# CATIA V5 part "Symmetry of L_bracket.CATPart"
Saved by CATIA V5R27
Part number: Symmetry of L_bracket
Bounding box of the stored display mesh (mm): x 0 to 76.2, y -76.2 to 0, z -16.637 to 16.637
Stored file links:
  \\triton.meca.polymtl.ca\usagers\zaoue\profiles\Desktop\varm_ass\structure prismatique\Symmetry of L_bracket.CATPart
  \\triton.meca.polymtl.ca\usagers\zaoue\profiles\Desktop\varm_ass\plaque moteur\L_bracket.CATPart
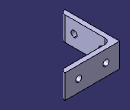
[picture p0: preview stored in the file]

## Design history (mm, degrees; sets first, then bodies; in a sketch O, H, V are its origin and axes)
Body1 (main body)
  Body2 "Corps du corps principal d'origine"
    Solid1: linked copy from another document
  Assemble1: tool Body2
